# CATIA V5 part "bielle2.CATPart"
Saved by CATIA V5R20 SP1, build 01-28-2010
Part number: bielle2
Bounding box of the stored display mesh (mm): x -5 to 5, y 36.117 to 129.589, z -67.105 to -7.266
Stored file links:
  E:\EDELI\gcausse\Edeli_2012_679_gcausse\bielle2.CATPart
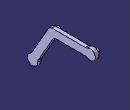
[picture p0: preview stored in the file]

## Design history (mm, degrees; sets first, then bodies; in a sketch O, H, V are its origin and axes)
Body1 (main body)
  Sketch1 on yz-plane, origin (0, 0, 0), H (0, 1, 0), V (0, 0, 1)
    line L1 (117.6905, -9.1829) -> (66.6415, -9.1829)
    point P2 (66.6415, -9.1829)
    line L2 (117.6905, -19.1829) -> (72.415, -19.1829)
    point P4 (72.415, -19.1829)
    line L3 (72.415, -19.1829) -> (49.7773, -58.3927)
    line L4 (66.6415, -9.1829) -> (41.117, -53.3927)
    arc A1 centre (42.9977, -60.1353) radius 7 from (41.117, -53.3927) to (49.7773, -58.3927) ccw
    point P7 (42.9977, -60.1353)
    arc A2 centre (122.5895, -14.1829) radius 7 from (117.6905, -9.1829) to (117.6905, -19.1829) cw
    point P8 (122.5895, -14.1829)
    circle A3 centre (69.5283, -14.1829) radius 2.5
    point P9 (69.5283, -14.1829)
    radius A3 = 2.5
    radius A2 = 7
    radius A1 = 7
    angle L4 L1 = 60
    distance L3 L4 = 10
    distance L1 L2 = 10
    distance P8 L2 = 5
    distance P7 L3 = 5
    distance P7 P9 = 53.0612 {= 50mm*3.12/2.94}
    horizontal: L1 H, L2 H
    equidistance: P2 P4 P9, L3 L4 P9, P7 P8 P9
  Pad1: profile Sketch1, direction (1, 0, 0), length 5
  Sketch2 on end face of Pad1, origin (5, 0, 0), H (0, 1, 0), V (0, 0, 1)
    circle A1 centre (69.5283, -14.1829) radius 2.5
    reference projected circle E1 centre (69.5283, -14.1829) radius 2.5 from edge [end face of Pad1 | face of Pad1 from Sketch1.A3]
    reference projected circle E2 centre (69.5283, -14.1829) radius 2.5 from edge [end face of Pad1 | face of Pad1 from Sketch1.A3]
    radius A1 = 2.5
    radius E2 = 2.5 (reference)
    concentricity: A1 E1
  Pad2: profile Sketch2, direction (-1, 0, 0), length 10
  Sketch3 on start face of Pad1, origin (0, 0, 0), H (0, -1, 0), V (0, 0, 1)
    circle A1 centre (-122.5895, -14.1829) radius 2.5
    reference projected arc E1 centre (-122.5895, -14.1829) radius 7 from (-117.6905, -9.1829) to (-117.6905, -19.1829) ccw from edge [start face of Pad1 | face of Pad1 from Sketch1.A2]
    reference projected arc E2 centre (-122.5895, -14.1829) radius 7 from (-117.6905, -9.1829) to (-117.6905, -19.1829) ccw from edge [start face of Pad1 | face of Pad1 from Sketch1.A2]
    radius A1 = 2.5
    radius E2 = 7 (reference)
    concentricity: A1 E1
  Pad3: profile Sketch3, direction (-1, 0, 0), length 5
  Fillet1: radius 5, on edge [face of Pad1 from Sketch1.L4 | face of Pad1 from Sketch1.L1]; edge [face of Pad1 from Sketch1.L1 | face of Pad1 from Sketch1.A2]; edge [face of Pad1 from Sketch1.A2 | face of Pad1 from Sketch1.L2]; edge [face of Pad1 from Sketch1.L2 | face of Pad1 from Sketch1.L3]; edge [face of Pad1 from Sketch1.L3 | face of Pad1 from Sketch1.A1]; edge [face of Pad1 from Sketch1.A1 | face of Pad1 from Sketch1.L4]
